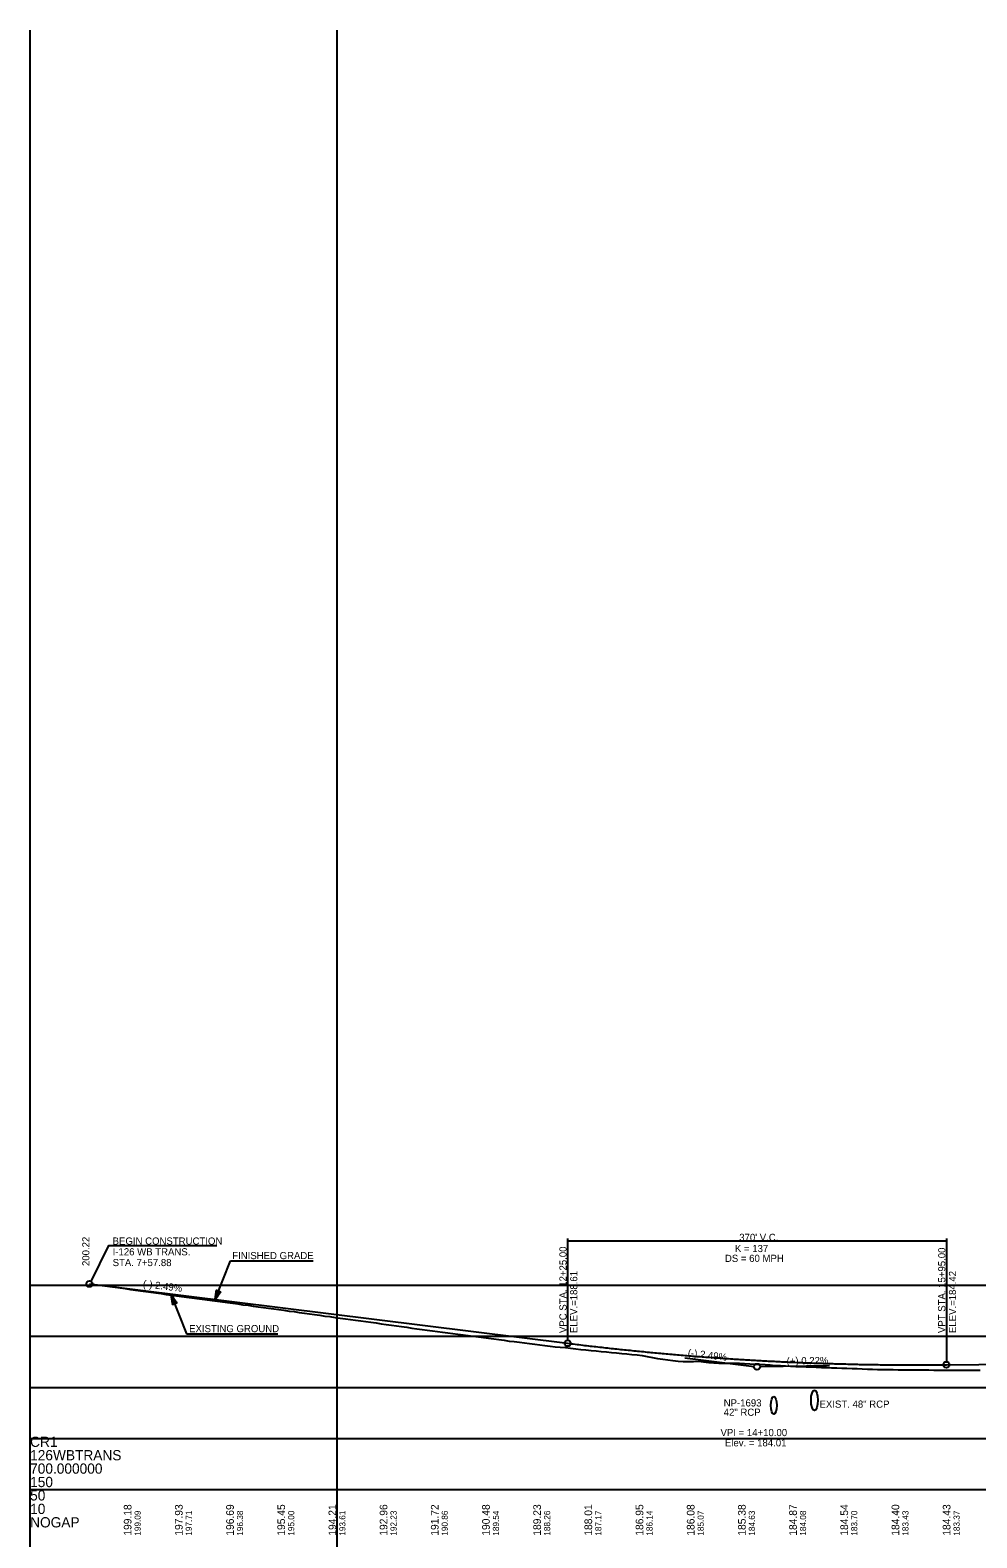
# Model space of a CAD drawing. Extents: x 69 to 2003113, y 512 to 837401.
# Drawn here: x 1888078 to 1889002, y 821803 to 823277 of the extents above; entities that cross this region are included whole.
import ezdxf

# ---------------------------------------------------------------- set-up
doc = ezdxf.new("R2010")
doc.units = 0
for name, color, linetype in [('BR_AUTO DIMENSION', 7, 'Continuous'), ('BR_BORDER LINES', 7, 'Continuous'), ('BR_CENTER LINE BASELINE', 7, 'Continuous'), ('BR_CONCRETE', 7, 'Continuous'), ('BR_GRID DOTS', 7, 'Continuous'), ('BR_GRID LINES', 7, 'Continuous'), ('BR_TEXT', 7, 'Continuous'), ('RD_HC_Points', 7, 'Continuous'), ('RD_PD_ALT1_TrvlWay', 7, 'Continuous'), ('RD_SHT_IplotShp', 7, 'Continuous'), ('RD_XS_PaveShd', 7, 'Continuous')]:
    doc.layers.add(name, color=color, linetype=linetype)

msp = doc.modelspace()

# ---------------------------------------------------------------- linework, layer by layer
at = {"layer": 'BR_AUTO DIMENSION'}
for p, q in [((1888077.5, 820550.1), (1888077.5, 823276.6)), ((1888377.5, 820550.1), (1888377.5, 823276.6)), ((1888077.5, 822050.1), (1889814.9, 822050.1)), ((1888077.5, 822000.1), (1889814.9, 822000.1)), ((1888077.5, 821950.1), (1889814.9, 821950.1)), ((1888077.5, 821900.1), (1889814.9, 821900.1)), ((1888077.5, 821850.1), (1889814.9, 821850.1))]:
    msp.add_line(p, q, dxfattribs=at)
at = {"layer": 'BR_BORDER LINES'}
msp.add_line((1888077.5, 821800.1), (1888077.5, 823050.1), dxfattribs=at)
at = {"layer": 'BR_CENTER LINE BASELINE'}
for p, q in [((1888717.1, 821979), (1888784.6, 821970.6)), ((1888858.5, 821971), (1888790.5, 821970.2))]:
    msp.add_line(p, q, dxfattribs=at)
for centre in [(1888135.4, 822051.2), (1888787.5, 821970.2)]:
    msp.add_circle(centre, 3, dxfattribs=at)
at = {"layer": 'BR_GRID DOTS'}
for p, q in [((1888602.5, 822095.7), (1888602.5, 821996.2)), ((1888602.5, 822093.2), (1888972.5, 822093.2)), ((1888972.5, 822095.7), (1888972.5, 821975.2))]:
    msp.add_line(p, q, dxfattribs=at)
msp.add_lwpolyline([(1888136.8, 822053), (1888154.4, 822088.6), (1888259.9, 822088.6)], dxfattribs=at)
for centre in [(1888602.5, 821993.2), (1888972.5, 821972.2)]:
    msp.add_circle(centre, 3, dxfattribs=at)
at = {"layer": 'BR_GRID LINES'}
for p, q in [((1888135.4, 822051.2), (1888602.5, 821993.2)), ((1888972.5, 821972.2), (1889347.5, 821976.4))]:
    msp.add_line(p, q, dxfattribs=at)
msp.add_spline([(1888602.5, 821993.2), (1888609.9, 821992.3), (1888617.3, 821991.4), (1888624.7, 821990.5), (1888632.1, 821989.7), (1888639.5, 821988.8), (1888646.9, 821988), (1888654.3, 821987.2), (1888661.7, 821986.5), (1888669.1, 821985.7), (1888676.5, 821985), (1888683.9, 821984.3), (1888691.3, 821983.6), (1888698.7, 821982.9), (1888706.1, 821982.3), (1888713.5, 821981.6), (1888720.9, 821981), (1888728.3, 821980.4), (1888735.7, 821979.9), (1888743.1, 821979.3), (1888750.5, 821978.8), (1888757.9, 821978.3), (1888765.3, 821977.8), (1888772.7, 821977.3), (1888780.1, 821976.9), (1888787.5, 821976.5), (1888794.9, 821976), (1888802.3, 821975.7), (1888809.7, 821975.3), (1888817.1, 821974.9), (1888824.5, 821974.6), (1888831.9, 821974.3), (1888839.3, 821974), (1888846.7, 821973.7), (1888854.1, 821973.5), (1888861.5, 821973.3), (1888868.9, 821973.1), (1888876.3, 821972.9), (1888883.7, 821972.7), (1888891.1, 821972.5), (1888898.5, 821972.4), (1888905.9, 821972.3), (1888913.3, 821972.2), (1888920.7, 821972.2), (1888928.1, 821972.1), (1888935.5, 821972.1), (1888942.9, 821972.1), (1888950.3, 821972.1), (1888957.7, 821972.1), (1888965.1, 821972.2), (1888972.5, 821972.2)], degree=3, dxfattribs=at)
at = {"layer": 'BR_TEXT'}
for points in [[(1888135.4, 822051.2), (1888140.4, 822050.5), (1888145.4, 822049.9), (1888150.4, 822049.3), (1888155.4, 822048.7), (1888160.4, 822048), (1888165.4, 822047.3), (1888170.4, 822046.6), (1888175.4, 822045.9), (1888180.4, 822045.2), (1888185.4, 822044.4), (1888190.4, 822043.7), (1888195.4, 822043), (1888200.4, 822042.4), (1888205.4, 822041.7), (1888210.4, 822040.9), (1888215.4, 822040.3), (1888220.4, 822039.6), (1888225.4, 822039), (1888230.4, 822038.3), (1888235.4, 822037.6), (1888240.4, 822036.9), (1888245.4, 822036.3), (1888250.4, 822035.6), (1888255.4, 822034.9), (1888260.4, 822034.2), (1888265.4, 822033.6), (1888270.4, 822032.9), (1888275.4, 822032.3), (1888280.4, 822031.6), (1888285.4, 822030.9), (1888290.4, 822030.3), (1888295.4, 822029.6), (1888300.4, 822028.9), (1888305.4, 822028.2), (1888310.4, 822027.5), (1888315.4, 822026.8), (1888320.4, 822026.1), (1888325.4, 822025.4), (1888330.4, 822024.7), (1888335.4, 822024.1), (1888340.4, 822023.4), (1888345.4, 822022.6), (1888350.4, 822021.9), (1888355.4, 822021.2), (1888360.4, 822020.5), (1888365.4, 822019.8), (1888370.4, 822019.2), (1888375.4, 822018.4), (1888380.4, 822017.8), (1888385.4, 822017.1), (1888390.4, 822016.4), (1888395.4, 822015.7), (1888400.4, 822015), (1888405.4, 822014.4), (1888410.4, 822013.7), (1888415.4, 822013), (1888420.4, 822012.3), (1888425.4, 822011.6), (1888430.4, 822010.9), (1888435.4, 822010.2), (1888440.4, 822009.5), (1888445.4, 822008.8), (1888450.4, 822008.1), (1888455.4, 822007.4), (1888460.4, 822006.8), (1888465.4, 822006.1), (1888470.4, 822005.4), (1888475.4, 822004.7), (1888480.4, 822004), (1888485.4, 822003.4), (1888490.4, 822002.8), (1888495.4, 822002.1), (1888500.4, 822001.4), (1888505.4, 822000.8), (1888510.4, 822000.1), (1888515.4, 821999.4), (1888520.4, 821998.8), (1888525.4, 821998.1), (1888530.4, 821997.4), (1888535.4, 821996.8), (1888540.4, 821996.1), (1888545.4, 821995.4), (1888550.4, 821994.8), (1888555.4, 821994.2), (1888560.4, 821993.6), (1888565.4, 821992.9), (1888570.4, 821992.3), (1888575.4, 821991.7), (1888580.4, 821991.1), (1888585.4, 821990.4), (1888590.4, 821989.8), (1888595.4, 821989.3), (1888600.4, 821988.9), (1888605.4, 821988.3), (1888610.4, 821987.8), (1888615.4, 821987.2), (1888620.4, 821986.7), (1888625.4, 821986.2), (1888630.4, 821985.7), (1888635.4, 821985.2)], [(1888635.4, 821985.2), (1888640.4, 821984.7), (1888645.4, 821984.2), (1888650.4, 821983.7), (1888655.4, 821983.2), (1888660.4, 821982.8), (1888665.4, 821982.3), (1888670.4, 821981.9), (1888675.4, 821981.2), (1888680.4, 821980.4), (1888685.4, 821979.3), (1888690.4, 821978.2), (1888695.4, 821977.7), (1888700.4, 821977), (1888705.4, 821976.4), (1888710.4, 821975.7), (1888715.4, 821975.3), (1888720.4, 821975.4), (1888725.4, 821975.4), (1888730.4, 821975.6), (1888735.4, 821975.2), (1888740.4, 821974.5), (1888745.4, 821974), (1888750.4, 821973.9), (1888755.4, 821973.8), (1888760.4, 821973.8), (1888765.4, 821973.8), (1888770.4, 821973.9), (1888775.4, 821973.4), (1888780.4, 821973.1), (1888785.4, 821972.8), (1888790.4, 821972.6), (1888795.4, 821972.3), (1888800.4, 821972), (1888805.4, 821971.6), (1888810.4, 821971.4), (1888815.4, 821971.1), (1888820.4, 821970.9), (1888825.4, 821970.6), (1888830.4, 821970.4), (1888835.4, 821970.2), (1888840.4, 821970), (1888845.4, 821969.7), (1888850.4, 821969.5), (1888855.4, 821969.4), (1888860.4, 821969.3), (1888865.4, 821969.1), (1888870.4, 821968.9), (1888875.4, 821968.7), (1888880.4, 821968.6), (1888885.4, 821968.4), (1888890.4, 821968.2), (1888895.4, 821968), (1888900.4, 821967.9), (1888905.4, 821967.7), (1888910.4, 821967.6), (1888915.4, 821967.6), (1888920.4, 821967.4), (1888925.4, 821967.3), (1888930.4, 821967.2), (1888935.4, 821967.1), (1888940.4, 821967.1), (1888945.4, 821967.1), (1888950.4, 821967.1), (1888955.4, 821967.1), (1888960.4, 821967), (1888965.4, 821967), (1888970.4, 821967), (1888975.4, 821967), (1888980.4, 821967), (1888985.4, 821967), (1888990.4, 821967), (1888995.4, 821967), (1889000.4, 821967), (1889005.4, 821967)]]:
    msp.add_lwpolyline(points, dxfattribs=at)
at = {"layer": 'RD_PD_ALT1_TrvlWay'}
for p, q in [((1888258.3, 822036), (1888273.2, 822073.9)), ((1888273.2, 822073.9), (1888354, 822073.9)), ((1888215.4, 822040.3), (1888230.4, 822002.3)), ((1888218.7, 822031.9), (1888215.4, 822040.3)), ((1888215.4, 822040.3), (1888220.8, 822032.7)), ((1888215.4, 822040.3), (1888216.6, 822031.1)), ((1888258.3, 822036), (1888259.5, 822045.2)), ((1888258.3, 822036), (1888259.5, 822045.2)), ((1888261.6, 822044.4), (1888258.3, 822036)), ((1888261.6, 822044.4), (1888258.3, 822036)), ((1888258.3, 822036), (1888263.6, 822043.5)), ((1888258.3, 822036), (1888263.6, 822043.5)), ((1888259.5, 822045.2), (1888263.6, 822043.5)), ((1888259.5, 822045.2), (1888263.6, 822043.5)), ((1888216.6, 822031.1), (1888220.8, 822032.7)), ((1888230.4, 822002.3), (1888319.6, 822002.3))]:
    msp.add_line(p, q, dxfattribs=at)
for points in [[(1888218.6, 822032), (1888215.5, 822039.8), (1888218.6, 822031.9), (1888215.6, 822039.4), (1888218.5, 822031.9), (1888215.6, 822039.1), (1888218.4, 822031.9), (1888215.7, 822038.8), (1888218.3, 822031.8), (1888215.7, 822038.3), (1888218.2, 822031.8), (1888215.8, 822037.8), (1888218.1, 822031.8), (1888215.9, 822037.4), (1888218, 822031.7), (1888215.9, 822036.9), (1888217.9, 822031.7), (1888216, 822036.5), (1888217.8, 822031.6), (1888216, 822036.2), (1888217.7, 822031.6), (1888216.1, 822035.7), (1888217.6, 822031.5), (1888216.2, 822035.1), (1888217.5, 822031.5), (1888216.2, 822034.6), (1888217.4, 822031.4), (1888216.3, 822034), (1888217.3, 822031.4), (1888216.4, 822033.5), (1888217.2, 822031.3), (1888216.5, 822033.1), (1888217.1, 822031.3), (1888216.5, 822032.7), (1888217, 822031.2), (1888216.6, 822032.2), (1888216.9, 822031.3), (1888216.6, 822031.6), (1888216.7, 822031.3)], [(1888215.7, 822039.7), (1888218.7, 822032), (1888215.8, 822039.5), (1888218.8, 822032.1), (1888216, 822039.2), (1888218.9, 822032.1), (1888216.2, 822039), (1888219, 822032.1), (1888216.4, 822038.8), (1888219.1, 822032.1), (1888216.6, 822038.5), (1888219.1, 822032.1), (1888216.8, 822038.2), (1888219.2, 822032.2), (1888217, 822037.9), (1888219.4, 822032.2), (1888217.2, 822037.6), (1888219.4, 822032.2), (1888217.5, 822037.2), (1888219.5, 822032.3), (1888217.7, 822036.9), (1888219.6, 822032.3), (1888217.9, 822036.6), (1888219.6, 822032.4), (1888218.3, 822036.1), (1888219.7, 822032.4), (1888218.5, 822035.8), (1888219.8, 822032.4), (1888218.8, 822035.4), (1888219.9, 822032.4), (1888219, 822035), (1888220, 822032.5), (1888219.2, 822034.7), (1888220.1, 822032.6), (1888219.5, 822034.4), (1888220.2, 822032.6), (1888219.8, 822034), (1888220.3, 822032.6), (1888220, 822033.7), (1888220.4, 822032.7), (1888220.2, 822033.5), (1888220.5, 822032.8), (1888220.7, 822032.7), (1888220.5, 822032.8)], [(1888261.5, 822044.3), (1888258.4, 822036.5), (1888261.4, 822044.3), (1888258.5, 822036.9), (1888261.3, 822044.3), (1888258.5, 822037.1), (1888261.2, 822044.4), (1888258.5, 822037.5), (1888261.1, 822044.4), (1888258.6, 822038), (1888261, 822044.5), (1888258.7, 822038.5), (1888260.9, 822044.5), (1888258.7, 822038.9), (1888260.8, 822044.5), (1888258.8, 822039.3), (1888260.7, 822044.5), (1888258.8, 822039.7), (1888260.7, 822044.6), (1888258.9, 822040.1), (1888260.5, 822044.6), (1888258.9, 822040.6), (1888260.4, 822044.7), (1888259, 822041.2), (1888260.3, 822044.8), (1888259.1, 822041.6), (1888260.2, 822044.8), (1888259.1, 822042.2), (1888260.1, 822044.8), (1888259.2, 822042.7), (1888260, 822044.9), (1888259.3, 822043.2), (1888259.9, 822044.9), (1888259.3, 822043.6), (1888259.8, 822045), (1888259.4, 822044.1), (1888259.7, 822045), (1888259.5, 822044.6), (1888259.6, 822045)], [(1888261.5, 822044.3), (1888258.4, 822036.5), (1888261.4, 822044.3), (1888258.5, 822036.9), (1888261.3, 822044.3), (1888258.5, 822037.1), (1888261.2, 822044.4), (1888258.5, 822037.5), (1888261.1, 822044.4), (1888258.6, 822038), (1888261, 822044.5), (1888258.7, 822038.5), (1888260.9, 822044.5), (1888258.7, 822038.9), (1888260.8, 822044.5), (1888258.8, 822039.3), (1888260.7, 822044.5), (1888258.8, 822039.7), (1888260.7, 822044.6), (1888258.9, 822040.1), (1888260.5, 822044.6), (1888258.9, 822040.6), (1888260.4, 822044.7), (1888259, 822041.2), (1888260.3, 822044.8), (1888259.1, 822041.6), (1888260.2, 822044.8), (1888259.1, 822042.2), (1888260.1, 822044.8), (1888259.2, 822042.7), (1888260, 822044.9), (1888259.3, 822043.2), (1888259.9, 822044.9), (1888259.3, 822043.6), (1888259.8, 822045), (1888259.4, 822044.1), (1888259.7, 822045), (1888259.5, 822044.6), (1888259.6, 822045)], [(1888258.5, 822036.5), (1888261.6, 822044.2), (1888258.7, 822036.8), (1888261.7, 822044.2), (1888258.8, 822037), (1888261.8, 822044.2), (1888259, 822037.2), (1888261.8, 822044.1), (1888259.2, 822037.5), (1888261.9, 822044.1), (1888259.4, 822037.7), (1888262, 822044.1), (1888259.6, 822038), (1888262.1, 822044.1), (1888259.9, 822038.4), (1888262.2, 822044), (1888260.1, 822038.7), (1888262.3, 822044), (1888260.3, 822039), (1888262.4, 822044), (1888260.5, 822039.3), (1888262.4, 822043.9), (1888260.8, 822039.7), (1888262.5, 822043.9), (1888261.1, 822040.1), (1888262.6, 822043.9), (1888261.3, 822040.4), (1888262.7, 822043.9), (1888261.6, 822040.8), (1888262.7, 822043.8), (1888261.9, 822041.2), (1888262.8, 822043.7), (1888262.1, 822041.5), (1888262.9, 822043.6), (1888262.3, 822041.8), (1888263, 822043.6), (1888262.6, 822042.3), (1888263.1, 822043.6), (1888262.8, 822042.5), (1888263.3, 822043.6), (1888263, 822042.7), (1888263.4, 822043.4), (1888263.5, 822043.5), (1888263.4, 822043.5)], [(1888258.5, 822036.5), (1888261.6, 822044.2), (1888258.7, 822036.8), (1888261.7, 822044.2), (1888258.8, 822037), (1888261.8, 822044.2), (1888259, 822037.2), (1888261.8, 822044.1), (1888259.2, 822037.5), (1888261.9, 822044.1), (1888259.4, 822037.7), (1888262, 822044.1), (1888259.6, 822038), (1888262.1, 822044.1), (1888259.9, 822038.4), (1888262.2, 822044), (1888260.1, 822038.7), (1888262.3, 822044), (1888260.3, 822039), (1888262.4, 822044), (1888260.5, 822039.3), (1888262.4, 822043.9), (1888260.8, 822039.7), (1888262.5, 822043.9), (1888261.1, 822040.1), (1888262.6, 822043.9), (1888261.3, 822040.4), (1888262.7, 822043.9), (1888261.6, 822040.8), (1888262.7, 822043.8), (1888261.9, 822041.2), (1888262.8, 822043.7), (1888262.1, 822041.5), (1888262.9, 822043.6), (1888262.3, 822041.8), (1888263, 822043.6), (1888262.6, 822042.3), (1888263.1, 822043.6), (1888262.8, 822042.5), (1888263.3, 822043.6), (1888263, 822042.7), (1888263.4, 822043.4), (1888263.5, 822043.5), (1888263.4, 822043.5)]]:
    msp.add_lwpolyline(points, dxfattribs=at)
at = {"layer": 'RD_XS_PaveShd'}
for centre, major_axis in [((1888803.9, 821932.5), (0, 8.75)), ((1888843.6, 821937.5), (0, 10))]:
    msp.add_ellipse(centre, major_axis=major_axis, ratio=0.326509, dxfattribs=at)

# ---------------------------------------------------------------- texts
at = {"layer": 'BR_BORDER LINES'}
for s, p in [('CR1', (1888077.5, 821891.9)), ('126WBTRANS', (1888077.5, 821878.8)), ('700.000000', (1888077.5, 821865.7)), ('150', (1888077.5, 821852.6)), ('50', (1888077.5, 821839.5)), ('10', (1888077.5, 821826.3)), ('NOGAP', (1888077.5, 821813.2))]:
    msp.add_text(s, height=10, dxfattribs=at).set_placement(p)
at = {"layer": 'BR_CENTER LINE BASELINE'}
for s, rotation, p in [('(-) 2.49%', 352.915, (1888187.4, 822048.1)), ('(-) 2.49%', 352.915, (1888719.6, 821980.7)), ('(+) 0.22%', 0.631, (1888816.5, 821972.5))]:
    msp.add_text(s, height=7, rotation=rotation, dxfattribs=at).set_placement(p)
at = {"layer": 'BR_CONCRETE'}
for s, height, p in [('VPC STA. 12+25.00 ', 7, (1888601.5, 822003.2)), ('VPT STA. 15+95.00 ', 7, (1888971.5, 822003.2)), ('ELEV.=188.61', 7, (1888612, 822003.2)), ('ELEV.=184.42', 7, (1888982, 822003.2)), ('199.09', 6, (1888185.5, 821805.1)), ('197.71', 6, (1888235.5, 821805.1)), ('196.38', 6, (1888285.5, 821805.1)), ('195.00', 6, (1888335.5, 821805.1)), ('193.61', 6, (1888385.5, 821805.1)), ('192.23', 6, (1888435.5, 821805.1)), ('190.86', 6, (1888485.5, 821805.1)), ('189.54', 6, (1888535.5, 821805.1)), ('188.26', 6, (1888585.5, 821805.1)), ('187.17', 6, (1888635.5, 821805.1)), ('186.14', 6, (1888685.5, 821805.1)), ('185.07', 6, (1888735.5, 821805.1)), ('184.63', 6, (1888785.5, 821805.1)), ('184.08', 6, (1888835.5, 821805.1)), ('183.70', 6, (1888885.5, 821805.1)), ('183.43', 6, (1888935.5, 821805.1)), ('183.37', 6, (1888985.5, 821805.1))]:
    msp.add_text(s, height=height, rotation=90, dxfattribs=at).set_placement(p)
at = {"layer": 'BR_GRID DOTS'}
for s, p in [("370' V.C.", (1888770.2, 822093.2)), ('K = 137', (1888766, 822082.3)), ('DS = 60 MPH', (1888756.2, 822072.7))]:
    msp.add_text(s, height=7, dxfattribs=at).set_placement(p)
at = {"layer": 'RD_HC_Points'}
for s, p in [('199.18', (1888176.5, 821805.1)), ('197.93', (1888226.5, 821805.1)), ('196.69', (1888276.5, 821805.1)), ('195.45', (1888326.5, 821805.1)), ('194.21', (1888376.5, 821805.1)), ('192.96', (1888426.5, 821805.1)), ('191.72', (1888476.5, 821805.1)), ('190.48', (1888526.5, 821805.1)), ('189.23', (1888576.5, 821805.1)), ('188.01', (1888626.5, 821805.1)), ('186.95', (1888676.5, 821805.1)), ('186.08', (1888726.5, 821805.1)), ('185.38', (1888776.5, 821805.1)), ('184.87', (1888826.5, 821805.1)), ('184.54', (1888876.5, 821805.1)), ('184.40', (1888926.5, 821805.1)), ('184.43', (1888976.5, 821805.1))]:
    msp.add_text(s, height=7.5, rotation=90, dxfattribs=at).set_placement(p)
at = {"layer": 'RD_PD_ALT1_TrvlWay'}
for s, p in [('FINISHED GRADE', (1888274.9, 822075.4)), ('EXISTING GROUND', (1888232.8, 822004))]:
    msp.add_text(s, height=7, dxfattribs=at).set_placement(p)
at = {"layer": 'RD_SHT_IplotShp'}
msp.add_text('200.22', height=7, rotation=90, dxfattribs=at).set_placement((1888135.4, 822068.7))
for s, p in [('BEGIN CONSTRUCTION', (1888158.1, 822089.6)), ('I-126 WB TRANS.', (1888158.1, 822079.1)), ('STA. 7+57.88', (1888158.1, 822068.6)), ('VPI = 14+10.00', (1888751.9, 821902.4)), ('Elev. = 184.01', (1888756.2, 821892.4))]:
    msp.add_text(s, height=7, dxfattribs=at).set_placement(p)
at = {"layer": 'RD_XS_PaveShd'}
for s, p in [('NP-1693', (1888755, 821931.4)), ('EXIST. 48" RCP', (1888848.6, 821930.2)), ('42" RCP', (1888755, 821922.3))]:
    msp.add_text(s, height=7, dxfattribs=at).set_placement(p)

doc.saveas('drawing.dxf')
